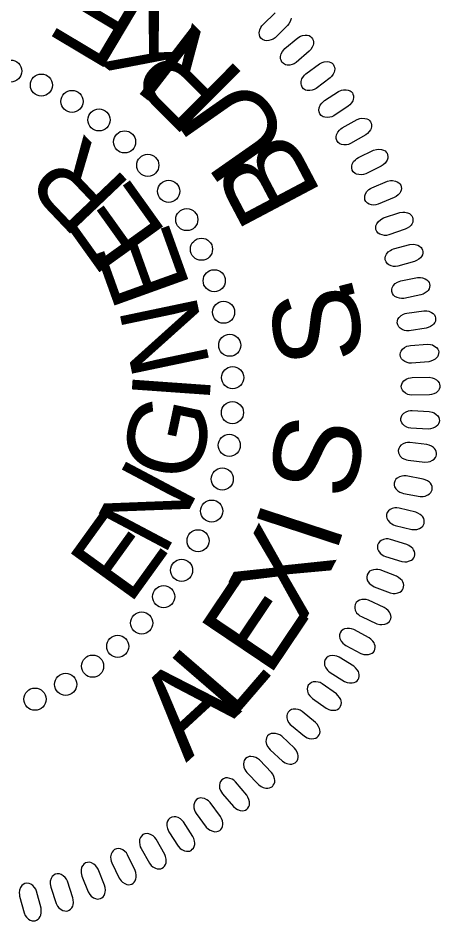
# Model space of a CAD drawing. Extents: x 477151 to 478666, y 496366 to 498184.
# Drawn here: x 477491.5 to 477522.1, y 497945.5 to 498010.8 of the extents above; entities that cross this region are included whole.
import ezdxf

# ---------------------------------------------------------------- set-up
doc = ezdxf.new("R2010")
doc.units = 0
doc.layers.add('Sheet PE Seal Cell', color=7, linetype='Continuous')

msp = doc.modelspace()

# ---------------------------------------------------------------- linework, layer by layer
at = {"layer": 'Sheet PE Seal Cell'}
msp.add_lwpolyline([(477511.289, 498010.834), (477511.274, 498010.735), (477511.212, 498010.583), (477511.124, 498010.416), (477511.026, 498010.289), (477510.125, 498009.412), (477509.987, 498009.311), (477509.855, 498009.247), (477509.678, 498009.2), (477509.5, 498009.184), (477509.375, 498009.199), (477509.223, 498009.27), (477509.105, 498009.365), (477509.03, 498009.5), (477508.994, 498009.61), (477508.977, 498009.77), (477509.016, 498009.974), (477509.099, 498010.148), (477509.172, 498010.258), (477509.255, 498010.359), (477510.139, 498011.209)], dxfattribs=at)
for points in [[(477510.838, 498008.617), (477511.774, 498009.41), (477511.965, 498009.524), (477512.106, 498009.575), (477512.308, 498009.599), (477512.454, 498009.596), (477512.588, 498009.561), (477512.686, 498009.508), (477512.774, 498009.435), (477512.831, 498009.336), (477512.885, 498009.226), (477512.908, 498009.108), (477512.899, 498008.963), (477512.877, 498008.866), (477512.807, 498008.718), (477512.708, 498008.555), (477512.602, 498008.436), (477511.648, 498007.617), (477511.504, 498007.525), (477511.368, 498007.469), (477511.189, 498007.434), (477511.009, 498007.429), (477510.886, 498007.452), (477510.739, 498007.532), (477510.626, 498007.634), (477510.56, 498007.774), (477510.531, 498007.886), (477510.524, 498008.047), (477510.577, 498008.248), (477510.67, 498008.416), (477510.75, 498008.522)], [(477512.36, 498006.79), (477513.345, 498007.524), (477513.542, 498007.625), (477513.686, 498007.666), (477513.889, 498007.678), (477514.035, 498007.666), (477514.166, 498007.623), (477514.26, 498007.563), (477514.343, 498007.485), (477514.394, 498007.384), (477514.441, 498007.27), (477514.457, 498007.15), (477514.439, 498007.007), (477514.411, 498006.911), (477514.331, 498006.767), (477514.223, 498006.612), (477514.108, 498006.499), (477513.105, 498005.742), (477512.956, 498005.659), (477512.817, 498005.611), (477512.636, 498005.588), (477512.457, 498005.594), (477512.335, 498005.624), (477512.193, 498005.714), (477512.087, 498005.822), (477512.031, 498005.966), (477512.008, 498006.08), (477512.011, 498006.241), (477512.076, 498006.438), (477512.18, 498006.6), (477512.266, 498006.701)], [(477513.704, 498004.855), (477514.732, 498005.525), (477514.936, 498005.614), (477515.081, 498005.646), (477515.285, 498005.645), (477515.429, 498005.624), (477515.558, 498005.573), (477515.648, 498005.507), (477515.726, 498005.424), (477515.77, 498005.32), (477515.811, 498005.203), (477515.818, 498005.083), (477515.791, 498004.94), (477515.758, 498004.847), (477515.669, 498004.709), (477515.551, 498004.561), (477515.43, 498004.454), (477514.381, 498003.762), (477514.227, 498003.688), (477514.085, 498003.65), (477513.903, 498003.638), (477513.725, 498003.655), (477513.605, 498003.693), (477513.468, 498003.792), (477513.37, 498003.907), (477513.322, 498004.053), (477513.307, 498004.168), (477513.32, 498004.329), (477513.397, 498004.522), (477513.511, 498004.677), (477513.604, 498004.772)], [(477514.995, 498002.887), (477516.063, 498003.49), (477516.272, 498003.566), (477516.419, 498003.589), (477516.622, 498003.575), (477516.765, 498003.545), (477516.89, 498003.486), (477516.976, 498003.415), (477517.049, 498003.327), (477517.086, 498003.22), (477517.119, 498003.101), (477517.119, 498002.981), (477517.083, 498002.841), (477517.043, 498002.749), (477516.946, 498002.616), (477516.82, 498002.477), (477516.692, 498002.378), (477515.602, 498001.753), (477515.443, 498001.689), (477515.3, 498001.66), (477515.117, 498001.659), (477514.94, 498001.687), (477514.822, 498001.733), (477514.693, 498001.839), (477514.602, 498001.961), (477514.563, 498002.11), (477514.556, 498002.226), (477514.579, 498002.385), (477514.668, 498002.572), (477514.791, 498002.72), (477514.889, 498002.809)], [(477516.161, 498000.735), (477517.265, 498001.27), (477517.478, 498001.332), (477517.627, 498001.347), (477517.829, 498001.32), (477517.969, 498001.28), (477518.091, 498001.214), (477518.172, 498001.138), (477518.239, 498001.045), (477518.27, 498000.936), (477518.295, 498000.816), (477518.287, 498000.695), (477518.243, 498000.558), (477518.197, 498000.469), (477518.092, 498000.343), (477517.957, 498000.21), (477517.823, 498000.12), (477516.696, 497999.565), (477516.534, 497999.511), (477516.389, 497999.491), (477516.206, 497999.502), (477516.032, 497999.541), (477515.917, 497999.594), (477515.794, 497999.709), (477515.712, 497999.835), (477515.682, 497999.986), (477515.682, 498000.103), (477515.715, 498000.261), (477515.816, 498000.442), (477515.948, 498000.581), (477516.051, 498000.665)], [(477517.142, 497998.557), (477518.278, 497999.023), (477518.494, 497999.071), (477518.643, 497999.076), (477518.843, 497999.037), (477518.981, 497998.989), (477519.098, 497998.915), (477519.174, 497998.834), (477519.235, 497998.737), (477519.259, 497998.626), (477519.277, 497998.504), (477519.262, 497998.384), (477519.209, 497998.249), (477519.158, 497998.164), (477519.045, 497998.045), (477518.901, 497997.922), (477518.762, 497997.84), (477517.603, 497997.356), (477517.437, 497997.313), (477517.291, 497997.301), (477517.109, 497997.324), (477516.938, 497997.374), (477516.827, 497997.434), (477516.712, 497997.556), (477516.637, 497997.688), (477516.617, 497997.841), (477516.624, 497997.957), (477516.667, 497998.112), (477516.779, 497998.287), (477516.92, 497998.418), (477517.028, 497998.494)], [(477517.99, 497996.367), (477519.153, 497996.76), (477519.372, 497996.796), (477519.521, 497996.791), (477519.718, 497996.739), (477519.853, 497996.682), (477519.965, 497996.602), (477520.036, 497996.515), (477520.09, 497996.415), (477520.107, 497996.303), (477520.117, 497996.18), (477520.094, 497996.061), (477520.033, 497995.93), (477519.977, 497995.848), (477519.857, 497995.737), (477519.706, 497995.622), (477519.562, 497995.55), (477518.374, 497995.14), (477518.207, 497995.107), (477518.059, 497995.105), (477517.88, 497995.138), (477517.712, 497995.199), (477517.605, 497995.266), (477517.498, 497995.395), (477517.431, 497995.531), (477517.422, 497995.685), (477517.435, 497995.8), (477517.488, 497995.953), (477517.611, 497996.12), (477517.76, 497996.242), (477517.872, 497996.312)], [(477518.716, 497994.131), (477519.9, 497994.45), (477520.122, 497994.472), (477520.27, 497994.458), (477520.463, 497994.394), (477520.595, 497994.328), (477520.701, 497994.241), (477520.766, 497994.151), (477520.815, 497994.047), (477520.825, 497993.934), (477520.827, 497993.81), (477520.797, 497993.694), (477520.728, 497993.567), (477520.666, 497993.488), (477520.539, 497993.384), (477520.382, 497993.28), (477520.233, 497993.217), (477519.022, 497992.882), (477518.853, 497992.859), (477518.706, 497992.867), (477518.529, 497992.912), (477518.365, 497992.983), (477518.262, 497993.056), (477518.164, 497993.192), (477518.105, 497993.332), (477518.105, 497993.486), (477518.126, 497993.6), (477518.189, 497993.749), (477518.321, 497993.908), (477518.478, 497994.02), (477518.595, 497994.083)], [(477519.234, 497991.815), (477520.436, 497992.059), (477520.659, 497992.067), (477520.806, 497992.043), (477520.995, 497991.967), (477521.121, 497991.894), (477521.222, 497991.799), (477521.281, 497991.705), (477521.323, 497991.599), (477521.326, 497991.486), (477521.32, 497991.362), (477521.283, 497991.248), (477521.206, 497991.125), (477521.14, 497991.051), (477521.007, 497990.955), (477520.843, 497990.861), (477520.691, 497990.807), (477519.461, 497990.549), (477519.29, 497990.537), (477519.145, 497990.554), (477518.97, 497990.61), (477518.811, 497990.691), (477518.714, 497990.771), (477518.624, 497990.912), (477518.574, 497991.055), (477518.584, 497991.21), (477518.612, 497991.322), (477518.683, 497991.467), (477518.826, 497991.617), (477518.989, 497991.72), (477519.11, 497991.774)], [(477519.681, 497989.487), (477520.897, 497989.656), (477521.118, 497989.649), (477521.265, 497989.616), (477521.448, 497989.529), (477521.57, 497989.447), (477521.665, 497989.347), (477521.718, 497989.249), (477521.753, 497989.141), (477521.749, 497989.027), (477521.736, 497988.904), (477521.692, 497988.792), (477521.606, 497988.675), (477521.536, 497988.605), (477521.397, 497988.517), (477521.227, 497988.434), (477521.072, 497988.39), (477519.829, 497988.209), (477519.658, 497988.208), (477519.513, 497988.234), (477519.343, 497988.3), (477519.189, 497988.392), (477519.096, 497988.478), (477519.016, 497988.625), (477518.976, 497988.771), (477518.995, 497988.924), (477519.03, 497989.035), (477519.11, 497989.174), (477519.262, 497989.315), (477519.431, 497989.407), (477519.555, 497989.454)], [(477519.935, 497987.146), (477521.158, 497987.238), (477521.379, 497987.218), (477521.523, 497987.176), (477521.701, 497987.077), (477521.818, 497986.988), (477521.905, 497986.883), (477521.953, 497986.781), (477521.981, 497986.67), (477521.969, 497986.557), (477521.949, 497986.436), (477521.897, 497986.328), (477521.805, 497986.215), (477521.73, 497986.149), (477521.586, 497986.071), (477521.411, 497985.998), (477521.254, 497985.964), (477520.001, 497985.862), (477519.831, 497985.872), (477519.688, 497985.906), (477519.522, 497985.984), (477519.374, 497986.084), (477519.288, 497986.176), (477519.216, 497986.328), (477519.185, 497986.476), (477519.214, 497986.628), (477519.256, 497986.735), (477519.345, 497986.87), (477519.506, 497987.001), (477519.68, 497987.083), (477519.806, 497987.121)], [(477520.058, 497984.824), (477521.285, 497984.839), (477521.505, 497984.804), (477521.646, 497984.754), (477521.817, 497984.644), (477521.927, 497984.548), (477522.009, 497984.437), (477522.049, 497984.333), (477522.071, 497984.221), (477522.052, 497984.109), (477522.024, 497983.988), (477521.966, 497983.883), (477521.866, 497983.778), (477521.788, 497983.716), (477521.638, 497983.647), (477521.46, 497983.585), (477521.301, 497983.561), (477520.045, 497983.538), (477519.875, 497983.558), (477519.734, 497983.602), (477519.574, 497983.689), (477519.433, 497983.799), (477519.352, 497983.896), (477519.29, 497984.052), (477519.269, 497984.201), (477519.307, 497984.351), (477519.355, 497984.457), (477519.453, 497984.585), (477519.621, 497984.706), (477519.8, 497984.776), (477519.929, 497984.807)], [(477520.062, 497982.436), (477521.287, 497982.373), (477521.504, 497982.325), (477521.641, 497982.266), (477521.805, 497982.145), (477521.909, 497982.042), (477521.983, 497981.927), (477522.018, 497981.82), (477522.032, 497981.707), (477522.006, 497981.597), (477521.97, 497981.478), (477521.905, 497981.377), (477521.801, 497981.277), (477521.718, 497981.222), (477521.565, 497981.162), (477521.382, 497981.111), (477521.222, 497981.097), (477519.967, 497981.153), (477519.798, 497981.184), (477519.662, 497981.236), (477519.507, 497981.333), (477519.373, 497981.453), (477519.298, 497981.554), (477519.246, 497981.713), (477519.234, 497981.864), (477519.282, 497982.011), (477519.337, 497982.113), (477519.442, 497982.235), (477519.618, 497982.345), (477519.801, 497982.404), (477519.931, 497982.427)], [(477519.767, 497978.839), (477520.986, 497978.7), (477521.207, 497978.712), (477521.353, 497978.748), (477521.534, 497978.84), (477521.654, 497978.924), (477521.746, 497979.027), (477521.797, 497979.126), (477521.83, 497979.235), (477521.822, 497979.349), (477521.806, 497979.472), (477521.759, 497979.582), (477521.672, 497979.697), (477521.6, 497979.766), (477521.458, 497979.849), (477521.286, 497979.929), (477521.13, 497979.969), (477519.883, 497980.12), (477519.712, 497980.116), (477519.568, 497980.087), (477519.399, 497980.016), (477519.248, 497979.921), (477519.158, 497979.833), (477519.08, 497979.684), (477519.044, 497979.538), (477519.066, 497979.384), (477519.104, 497979.275), (477519.189, 497979.137), (477519.344, 497978.999), (477519.515, 497978.912), (477519.64, 497978.868)], [(477519.422, 497976.435), (477520.63, 497976.22), (477520.852, 497976.218), (477520.999, 497976.245), (477521.186, 497976.326), (477521.311, 497976.402), (477521.409, 497976.499), (477521.466, 497976.595), (477521.506, 497976.702), (477521.505, 497976.816), (477521.497, 497976.939), (477521.457, 497977.052), (477521.376, 497977.173), (477521.309, 497977.246), (477521.173, 497977.338), (477521.007, 497977.428), (477520.854, 497977.479), (477519.618, 497977.706), (477519.447, 497977.714), (477519.302, 497977.694), (477519.129, 497977.634), (477518.972, 497977.548), (477518.876, 497977.466), (477518.79, 497977.322), (477518.744, 497977.178), (477518.757, 497977.024), (477518.788, 497976.912), (477518.864, 497976.77), (477519.009, 497976.623), (477519.175, 497976.525), (477519.297, 497976.473)], [(477518.833, 497974.123), (477520.025, 497973.833), (477520.247, 497973.817), (477520.395, 497973.834), (477520.586, 497973.903), (477520.716, 497973.972), (477520.82, 497974.062), (477520.883, 497974.154), (477520.93, 497974.259), (477520.936, 497974.372), (477520.936, 497974.496), (477520.903, 497974.611), (477520.83, 497974.737), (477520.767, 497974.814), (477520.638, 497974.914), (477520.477, 497975.015), (477520.328, 497975.075), (477519.108, 497975.379), (477518.939, 497975.398), (477518.792, 497975.386), (477518.616, 497975.338), (477518.454, 497975.262), (477518.353, 497975.186), (477518.258, 497975.048), (477518.203, 497974.907), (477518.207, 497974.753), (477518.231, 497974.639), (477518.297, 497974.492), (477518.433, 497974.336), (477518.592, 497974.228), (477518.711, 497974.169)], [(477518.128, 497971.877), (477519.299, 497971.513), (477519.519, 497971.483), (477519.668, 497971.491), (477519.864, 497971.548), (477519.997, 497971.608), (477520.106, 497971.691), (477520.176, 497971.779), (477520.228, 497971.881), (477520.242, 497971.993), (477520.249, 497972.117), (477520.224, 497972.234), (477520.159, 497972.364), (477520.101, 497972.445), (477519.978, 497972.554), (477519.825, 497972.664), (477519.679, 497972.733), (477518.481, 497973.114), (477518.312, 497973.143), (477518.166, 497973.141), (477517.987, 497973.103), (477517.82, 497973.038), (477517.715, 497972.968), (477517.612, 497972.836), (477517.548, 497972.699), (477517.541, 497972.545), (477517.558, 497972.43), (477517.615, 497972.279), (477517.742, 497972.115), (477517.894, 497971.997), (477518.008, 497971.93)], [(477517.316, 497969.685), (477518.461, 497969.247), (477518.68, 497969.204), (477518.829, 497969.203), (477519.027, 497969.247), (477519.165, 497969.299), (477519.279, 497969.375), (477519.354, 497969.458), (477519.412, 497969.557), (477519.433, 497969.668), (477519.448, 497969.79), (477519.43, 497969.91), (477519.374, 497970.043), (477519.321, 497970.127), (477519.205, 497970.244), (477519.058, 497970.364), (477518.918, 497970.441), (477517.746, 497970.896), (477517.58, 497970.936), (477517.433, 497970.943), (477517.252, 497970.917), (477517.082, 497970.862), (477516.973, 497970.8), (477516.861, 497970.674), (477516.789, 497970.542), (477516.773, 497970.388), (477516.782, 497970.272), (477516.83, 497970.118), (477516.946, 497969.946), (477517.089, 497969.819), (477517.199, 497969.745)], [(477516.389, 497967.519), (477517.507, 497967.01), (477517.721, 497966.953), (477517.87, 497966.942), (477518.071, 497966.974), (477518.211, 497967.017), (477518.33, 497967.086), (477518.41, 497967.164), (477518.474, 497967.259), (477518.503, 497967.369), (477518.526, 497967.49), (477518.514, 497967.61), (477518.467, 497967.747), (477518.419, 497967.834), (477518.311, 497967.958), (477518.172, 497968.086), (477518.036, 497968.173), (477516.896, 497968.701), (477516.732, 497968.75), (477516.587, 497968.767), (477516.404, 497968.752), (477516.231, 497968.708), (477516.118, 497968.652), (477515.998, 497968.535), (477515.918, 497968.407), (477515.893, 497968.254), (477515.894, 497968.138), (477515.932, 497967.981), (477516.037, 497967.803), (477516.173, 497967.666), (477516.278, 497967.586)], [(477515.252, 497965.44), (477516.335, 497964.863), (477516.545, 497964.792), (477516.693, 497964.772), (477516.896, 497964.791), (477517.039, 497964.826), (477517.162, 497964.887), (477517.246, 497964.96), (477517.317, 497965.05), (477517.352, 497965.158), (477517.381, 497965.278), (477517.378, 497965.399), (477517.339, 497965.538), (477517.298, 497965.628), (477517.197, 497965.758), (477517.067, 497965.895), (477516.937, 497965.99), (477515.832, 497966.588), (477515.672, 497966.649), (477515.527, 497966.674), (477515.345, 497966.671), (477515.168, 497966.638), (477515.052, 497966.59), (477514.925, 497966.479), (477514.837, 497966.356), (477514.802, 497966.206), (477514.797, 497966.09), (477514.824, 497965.931), (477514.918, 497965.746), (477515.045, 497965.602), (477515.145, 497965.514)], [(477514.11, 497963.483), (477515.154, 497962.838), (477515.361, 497962.755), (477515.507, 497962.726), (477515.71, 497962.732), (477515.855, 497962.758), (477515.981, 497962.811), (477516.071, 497962.879), (477516.147, 497962.964), (477516.188, 497963.069), (477516.225, 497963.187), (477516.229, 497963.307), (477516.199, 497963.45), (477516.163, 497963.542), (477516.071, 497963.678), (477515.95, 497963.823), (477515.826, 497963.926), (477514.761, 497964.593), (477514.605, 497964.663), (477514.462, 497964.697), (477514.28, 497964.705), (477514.102, 497964.684), (477513.982, 497964.643), (477513.849, 497964.54), (477513.754, 497964.423), (477513.709, 497964.276), (477513.697, 497964.16), (477513.715, 497964), (477513.796, 497963.809), (477513.914, 497963.656), (477514.008, 497963.564)], [(477512.828, 497961.599), (477513.829, 497960.89), (477514.03, 497960.793), (477514.174, 497960.755), (477514.377, 497960.749), (477514.524, 497960.765), (477514.653, 497960.81), (477514.745, 497960.872), (477514.827, 497960.953), (477514.875, 497961.055), (477514.92, 497961.171), (477514.932, 497961.29), (477514.91, 497961.433), (477514.88, 497961.528), (477514.797, 497961.67), (477514.685, 497961.822), (477514.568, 497961.933), (477513.546, 497962.665), (477513.395, 497962.745), (477513.255, 497962.788), (477513.073, 497962.808), (477512.895, 497962.797), (477512.773, 497962.764), (477512.633, 497962.67), (477512.53, 497962.559), (477512.477, 497962.414), (477512.458, 497962.3), (477512.465, 497962.139), (477512.535, 497961.944), (477512.642, 497961.784), (477512.731, 497961.685)], [(477511.306, 497959.635), (477512.261, 497958.864), (477512.454, 497958.756), (477512.596, 497958.708), (477512.799, 497958.689), (477512.945, 497958.696), (477513.078, 497958.733), (477513.175, 497958.79), (477513.26, 497958.864), (477513.315, 497958.964), (477513.367, 497959.076), (477513.386, 497959.195), (477513.374, 497959.339), (477513.35, 497959.435), (477513.275, 497959.582), (477513.173, 497959.741), (477513.063, 497959.859), (477512.09, 497960.654), (477511.944, 497960.743), (477511.807, 497960.795), (477511.627, 497960.826), (477511.447, 497960.827), (477511.325, 497960.801), (477511.179, 497960.716), (477511.07, 497960.612), (477511.007, 497960.471), (477510.98, 497960.358), (477510.978, 497960.197), (477511.035, 497959.997), (477511.132, 497959.832), (477511.214, 497959.728)], [(477509.76, 497957.895), (477510.665, 497957.066), (477510.851, 497956.946), (477510.99, 497956.889), (477511.191, 497956.858), (477511.337, 497956.855), (477511.472, 497956.884), (477511.572, 497956.934), (477511.662, 497957.004), (477511.723, 497957.099), (477511.782, 497957.208), (477511.809, 497957.325), (477511.805, 497957.47), (477511.787, 497957.568), (477511.722, 497957.719), (477511.63, 497957.884), (477511.528, 497958.008), (477510.606, 497958.863), (477510.467, 497958.961), (477510.333, 497959.022), (477510.155, 497959.063), (477509.976, 497959.076), (477509.852, 497959.058), (477509.701, 497958.982), (477509.586, 497958.885), (477509.515, 497958.748), (477509.481, 497958.637), (477509.468, 497958.476), (477509.512, 497958.274), (477509.599, 497958.102), (477509.675, 497957.993)], [(477508.09, 497956.246), (477508.941, 497955.361), (477509.12, 497955.229), (477509.254, 497955.164), (477509.453, 497955.12), (477509.599, 497955.109), (477509.735, 497955.129), (477509.838, 497955.173), (477509.933, 497955.236), (477510, 497955.328), (477510.065, 497955.433), (477510.099, 497955.549), (477510.105, 497955.693), (477510.093, 497955.792), (477510.038, 497955.947), (477509.957, 497956.117), (477509.862, 497956.248), (477508.996, 497957.158), (477508.862, 497957.265), (477508.733, 497957.334), (477508.558, 497957.387), (477508.381, 497957.41), (477508.255, 497957.4), (477508.1, 497957.335), (477507.979, 497957.245), (477507.899, 497957.113), (477507.858, 497957.004), (477507.835, 497956.844), (477507.867, 497956.639), (477507.943, 497956.463), (477508.011, 497956.349)], [(477506.31, 497954.709), (477507.104, 497953.773), (477507.274, 497953.63), (477507.404, 497953.557), (477507.6, 497953.5), (477507.744, 497953.48), (477507.882, 497953.491), (477507.987, 497953.529), (477508.086, 497953.586), (477508.158, 497953.674), (477508.23, 497953.774), (477508.271, 497953.887), (477508.286, 497954.031), (477508.28, 497954.13), (477508.235, 497954.288), (477508.164, 497954.464), (477508.079, 497954.6), (477507.271, 497955.563), (477507.145, 497955.678), (477507.019, 497955.755), (477506.848, 497955.819), (477506.673, 497955.853), (477506.547, 497955.851), (477506.388, 497955.795), (477506.261, 497955.713), (477506.173, 497955.587), (477506.126, 497955.481), (477506.093, 497955.322), (477506.112, 497955.116), (477506.177, 497954.935), (477506.238, 497954.817)], [(477504.415, 497953.278), (477505.148, 497952.294), (477505.309, 497952.141), (477505.434, 497952.06), (477505.625, 497951.99), (477505.769, 497951.961), (477505.906, 497951.964), (477506.014, 497951.994), (477506.116, 497952.046), (477506.194, 497952.129), (477506.272, 497952.225), (477506.32, 497952.334), (477506.344, 497952.477), (477506.345, 497952.577), (477506.309, 497952.737), (477506.25, 497952.917), (477506.173, 497953.058), (477505.428, 497954.07), (477505.308, 497954.193), (477505.188, 497954.277), (477505.021, 497954.352), (477504.848, 497954.397), (477504.722, 497954.403), (477504.561, 497954.357), (477504.429, 497954.283), (477504.333, 497954.162), (477504.279, 497954.059), (477504.237, 497953.904), (477504.242, 497953.696), (477504.296, 497953.512), (477504.349, 497953.39)], [(477502.431, 497951.944), (477503.101, 497950.916), (477503.252, 497950.753), (477503.372, 497950.664), (477503.559, 497950.584), (477503.7, 497950.545), (477503.838, 497950.54), (477503.947, 497950.563), (477504.052, 497950.608), (477504.134, 497950.686), (477504.218, 497950.776), (477504.274, 497950.883), (477504.306, 497951.024), (477504.313, 497951.123), (477504.288, 497951.286), (477504.239, 497951.469), (477504.172, 497951.614), (477503.492, 497952.672), (477503.38, 497952.801), (477503.266, 497952.894), (477503.104, 497952.978), (477502.934, 497953.035), (477502.809, 497953.048), (477502.644, 497953.012), (477502.508, 497952.947), (477502.405, 497952.832), (477502.345, 497952.733), (477502.292, 497952.58), (477502.286, 497952.373), (477502.327, 497952.186), (477502.372, 497952.061)], [(477500.416, 497950.756), (477501.02, 497949.688), (477501.161, 497949.515), (477501.275, 497949.419), (477501.456, 497949.327), (477501.595, 497949.279), (477501.732, 497949.265), (477501.842, 497949.282), (477501.95, 497949.32), (477502.037, 497949.392), (477502.127, 497949.477), (477502.188, 497949.58), (477502.23, 497949.719), (477502.243, 497949.818), (477502.228, 497949.982), (477502.191, 497950.167), (477502.132, 497950.317), (477501.521, 497951.414), (477501.417, 497951.551), (477501.309, 497951.65), (477501.153, 497951.745), (477500.986, 497951.811), (477500.862, 497951.833), (477500.696, 497951.808), (477500.556, 497951.751), (477500.446, 497951.643), (477500.379, 497951.548), (477500.318, 497951.399), (477500.298, 497951.192), (477500.327, 497951.003), (477500.366, 497950.875)], [(477498.305, 497949.696), (477498.841, 497948.592), (477498.97, 497948.411), (477499.077, 497948.308), (477499.253, 497948.205), (477499.389, 497948.148), (477499.524, 497948.126), (477499.636, 497948.136), (477499.745, 497948.166), (477499.837, 497948.234), (477499.932, 497948.313), (477500, 497948.412), (477500.05, 497948.548), (477500.07, 497948.645), (477500.064, 497948.809), (477500.04, 497948.997), (477499.99, 497949.151), (477499.448, 497950.284), (477499.354, 497950.427), (477499.252, 497950.533), (477499.102, 497950.637), (477498.94, 497950.713), (477498.818, 497950.743), (477498.651, 497950.728), (477498.507, 497950.681), (477498.39, 497950.579), (477498.318, 497950.489), (477498.247, 497950.344), (477498.214, 497950.139), (477498.232, 497949.948), (477498.262, 497949.819)], [(477496.133, 497948.733), (477496.598, 497947.598), (477496.716, 497947.41), (477496.817, 497947.3), (477496.986, 497947.186), (477497.117, 497947.121), (477497.251, 497947.09), (477497.363, 497947.093), (477497.475, 497947.117), (477497.57, 497947.178), (477497.669, 497947.251), (477497.744, 497947.345), (477497.803, 497947.478), (477497.828, 497947.575), (477497.834, 497947.738), (477497.82, 497947.927), (477497.781, 497948.083), (477497.311, 497949.249), (477497.226, 497949.397), (477497.131, 497949.509), (477496.988, 497949.623), (477496.831, 497949.709), (477496.711, 497949.746), (477496.543, 497949.742), (477496.397, 497949.704), (477496.274, 497949.61), (477496.196, 497949.524), (477496.116, 497949.384), (477496.07, 497949.182), (477496.075, 497948.99), (477496.098, 497948.859)], [(477493.88, 497947.936), (477494.274, 497946.774), (477494.379, 497946.578), (477494.473, 497946.462), (477494.634, 497946.337), (477494.761, 497946.264), (477494.893, 497946.225), (477495.005, 497946.221), (477495.118, 497946.238), (477495.217, 497946.293), (477495.321, 497946.36), (477495.401, 497946.449), (477495.468, 497946.578), (477495.499, 497946.672), (477495.515, 497946.836), (477495.514, 497947.025), (477495.484, 497947.183), (477495.088, 497948.376), (477495.012, 497948.529), (477494.925, 497948.647), (477494.789, 497948.769), (477494.638, 497948.866), (477494.521, 497948.91), (477494.353, 497948.917), (477494.204, 497948.887), (477494.076, 497948.802), (477493.993, 497948.721), (477493.904, 497948.586), (477493.846, 497948.387), (477493.839, 497948.195), (477493.853, 497948.063)], [(477491.623, 497947.285), (477491.942, 497946.1), (477492.036, 497945.899), (477492.122, 497945.777), (477492.275, 497945.642), (477492.398, 497945.562), (477492.527, 497945.514), (477492.638, 497945.503), (477492.752, 497945.513), (477492.854, 497945.562), (477492.962, 497945.621), (477493.048, 497945.706), (477493.122, 497945.83), (477493.16, 497945.923), (477493.186, 497946.084), (477493.196, 497946.274), (477493.177, 497946.433), (477492.857, 497947.649), (477492.791, 497947.806), (477492.71, 497947.93), (477492.583, 497948.06), (477492.439, 497948.166), (477492.324, 497948.218), (477492.156, 497948.234), (477492.007, 497948.214), (477491.873, 497948.137), (477491.785, 497948.062), (477491.688, 497947.932), (477491.617, 497947.738), (477491.599, 497947.547), (477491.604, 497947.414)]]:
    msp.add_lwpolyline(points, close=True, dxfattribs=at)
for centre in [(477490.972, 498006.994), (477493.204, 498005.978), (477495.419, 498004.798), (477497.374, 498003.462), (477499.227, 498001.873), (477500.91, 498000.177), (477502.418, 497998.297), (477503.735, 497996.252), (477504.797, 497994.108), (477505.717, 497991.824), (477506.396, 497989.547), (477506.848, 497987.158), (477507.053, 497984.815), (477507.042, 497982.281), (477506.808, 497979.917), (477506.302, 497977.475), (477505.538, 497975.158), (477504.549, 497973.011), (477503.357, 497970.876), (477502.054, 497968.967), (477500.468, 497967.059), (477498.732, 497965.371), (477496.908, 497963.937), (477494.959, 497962.621), (477492.735, 497961.549)]:
    msp.add_circle(centre, 0.801, dxfattribs=at)

# ---------------------------------------------------------------- texts
for s, height, rotation, p in [('E', 6.236, 149.19094, (477501.475, 498012.29)), ('K', 6.236, 142.34528, (477505.287, 498009.382)), ('R', 6.236, 135.07025, (477508.102, 498006.512)), ('U', 6.236, 124.97041, (477511.42, 498002.022)), ('R', 5.669, 133.58624, (477499.807, 497998.701)), ('B', 6.236, 117.85357, (477513.568, 497998.061)), ('E', 5.669, 125.64644, (477502.37, 497995.24)), ('E', 5.669, 109.76685, (477504.043, 497991.364)), ('.', 6.236, 104.15095, (477516.076, 497990.169)), ('S', 6.236, 97.30529, (477516.584, 497986.162)), ('N', 5.669, 101.82705, (477505.45, 497985.655)), ('I', 5.669, 85.94746, (477505.362, 497982.863)), ('G', 5.669, 78.00766, (477504.464, 497977.055)), ('S', 6.236, 78.7101, (477515.678, 497975.817)), ('N', 5.669, 62.12806, (477502.07, 497971.781)), ('E', 5.669, 54.18827, (477499.575, 497968.268)), ('I', 6.236, 71.86444, (477514.505, 497971.963)), ('X', 6.236, 62.91712, (477512.128, 497966.838)), ('E', 6.236, 56.07146, (477509.653, 497963.059)), ('L', 6.236, 49.2258, (477506.974, 497959.947)), ('A', 6.236, 42.60613, (477503.68, 497956.924))]:
    msp.add_text(s, height=height, rotation=rotation, dxfattribs=at).set_placement(p)

doc.saveas('drawing.dxf')
